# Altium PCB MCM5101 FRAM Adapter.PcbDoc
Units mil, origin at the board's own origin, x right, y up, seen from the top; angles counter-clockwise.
Board outline 630 x 1120 mil, 2 copper layers (Top Layer, Bottom Layer); 4 components, 17 nets, 52 pads, 5 vias.
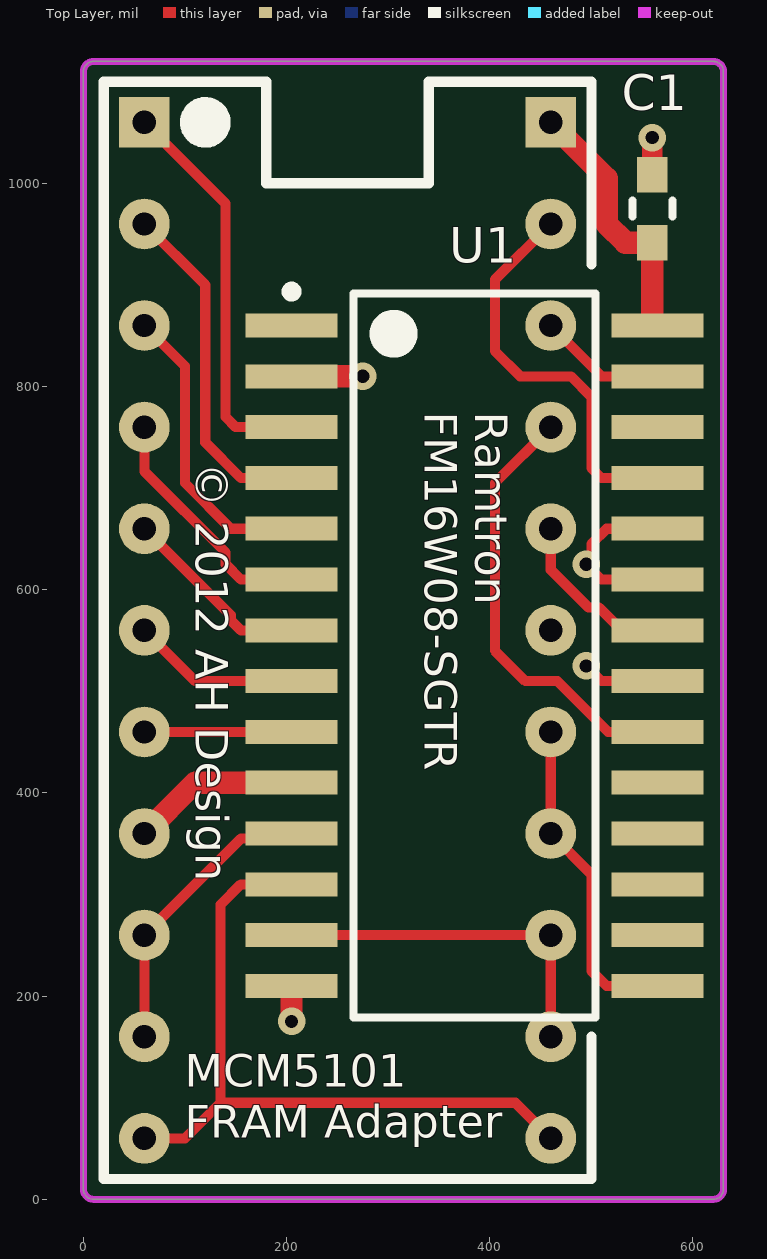
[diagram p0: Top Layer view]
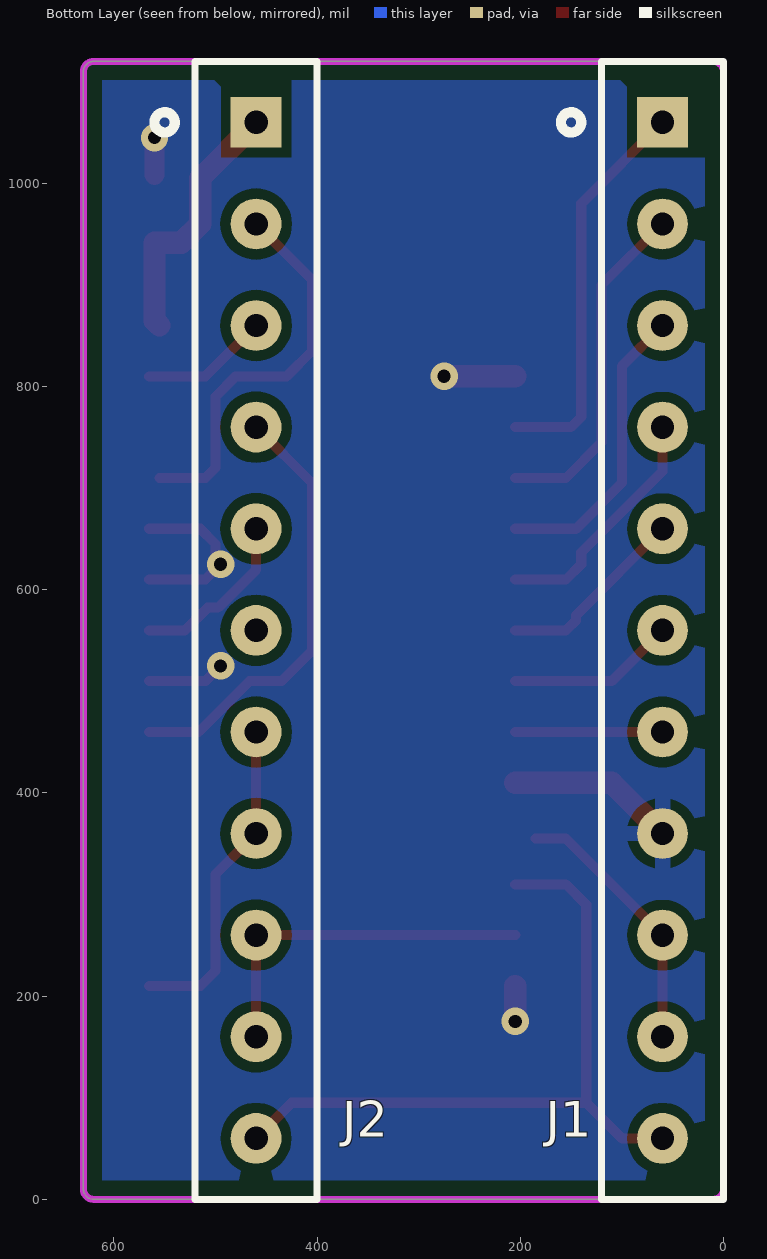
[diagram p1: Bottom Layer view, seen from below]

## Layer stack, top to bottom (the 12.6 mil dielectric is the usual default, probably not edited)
Top Layer: signal copper 1.4
Dielectric: dielectric 12.6, FR-4, Dk 4.8
Bottom Layer: signal copper 1.4

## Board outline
0,10 ccw(c10,10) 10,0 620,0 ccw(c620,10) 630,10 630,1110 ccw(c620,1110) 620,1120 10,1120 ccw(c10,1110) 0,1110

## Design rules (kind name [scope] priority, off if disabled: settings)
AcuteAngle [All] p1: minimum=6.00000000000000E+0001 checktracksonly=FALSE
Clearance Clearance_outline [OnLayer('Keep-Out Layer')] p1: gap=15
Clearance [All] p2: gap=10
MinimumAnnularRing [All] p1: minimumring=7
MinimumSolderMaskSliver [All] p1: minsoldermaskwidth=4
PolygonConnect PolygonConnect_1 [IsVia] p1: connectstyle=Direct reliefconductorwidth=10 reliefentries=4 polygonreliefangle="90 Angle"
PolygonConnect [All] p2: connectstyle=Relief reliefconductorwidth=15 reliefentries=4 polygonreliefangle="90 Angle"
RoomDefinition "MCM5101 FRAM Adapter" [InComponentClass('MCM5101 FRAM Adapter')] p1: confinementstyle=ConfineIn formatcopy=TRUE lockcomponents=FALSE outline -15,-15 635,-15 635,1135 -15,1135
RoutingVias [All] p1: holewidth=13 width=27 viastyle="Through Hole" minholewidth=13 minwidth=27 maxholewidth=28 maxwidth=50
SilkToSilkClearance [All] p1: silktosilkclearance=0
SilkscreenOverComponentPads [All] p1: minsilkscreentomaskgap=3
SolderMaskExpansion [All] p1: expansion=3
Width [All] p1: maxlimit=250 minlimit=10 preferedwidth=10
25 further rules are at their usual default settings.

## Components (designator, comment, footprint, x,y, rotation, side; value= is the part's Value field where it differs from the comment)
C1 "0.1uF" CC0603 560,975 r270 top
J1 "TS-111-T-AA" SAMTEC_TS-111-XX 60,560 r270 bottom
J2 "TS-111-T-AA" SAMTEC_TS-111-XX 460,560 r270 bottom
U1 "FM16W08-SGTR" SOIC127P1030X264-28N 385,535 r0 top

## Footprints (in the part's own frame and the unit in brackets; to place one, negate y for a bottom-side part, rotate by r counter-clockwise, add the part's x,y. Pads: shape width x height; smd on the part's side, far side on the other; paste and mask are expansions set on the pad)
CC0603 [mil] "Chip Capacitor, Body 1.6x0.8mm, IPC Medium Density"
  rect 35x30 smd: 1(-33.46,0) 2(33.46,0)
  silkscreen extent -8,-20 8,20, body extent -33,-19 33,19, height 24
SAMTEC_TS-111-XX [mil] "Samtec TS-111-XX series footprint"
  rect 50x50 hole 23: 1(-500,0)
  round 50 hole 23: 2(-400,0) 3(-300,0) 4(-200,0) 5(-100,0) 6(0,0) 7(100,0) 8(200,0) 9(300,0) 10(400,0) 11(500,0)
  silkscreen extent -560,-100 560,60, body extent -550,-50 550,50, height 325
SOIC127P1030X264-28N [mm] "SOIC, 28-Leads, Body 18.1x7.6mm (max), Pitch 1.27mm, IPC Medium Density"
  rect 2.3x0.6 smd: 1(-4.575,8.255) 2(-4.575,6.985) 3(-4.575,5.715) 4(-4.575,4.445) 5(-4.575,3.175) 6(-4.575,1.905) 7(-4.575,0.635) 8(-4.575,-0.635) 9(-4.575,-1.905) 10(-4.575,-3.175) 11(-4.575,-4.445) 12(-4.575,-5.715) 13(-4.575,-6.985) 14(-4.575,-8.255) 15(4.575,-8.255) 16(4.575,-6.985) 17(4.575,-5.715) 18(4.575,-4.445) 19(4.575,-3.175) 20(4.575,-1.905) 21(4.575,-0.635) 22(4.575,0.635) 23(4.575,1.905) 24(4.575,3.175) 25(4.575,4.445) 26(4.575,5.715) 27(4.575,6.985) 28(4.575,8.255)
  silkscreen extent -4.7,-9.05 3.03,9.23, body extent -3.79,-9.04 3.8,9.04, height 2.64

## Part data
C1: library part 0.1uF,10V,CC0603,X7R,+/-20%, "0.1uF 10V, in a CC0603, X7R ,+/-20%,LF"
J1 J2: library part Samtec_TS-111-T-AA, "PRECISION MACHINED TERMINAL STRIP, 0.018\" diameter post"
U1: "IC FRAM 64KBIT (8Kx8) 70NS 28SOIC"

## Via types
v1: diameter 27, hole 13, Top Layer to Bottom Layer, tented both sides, 5 vias

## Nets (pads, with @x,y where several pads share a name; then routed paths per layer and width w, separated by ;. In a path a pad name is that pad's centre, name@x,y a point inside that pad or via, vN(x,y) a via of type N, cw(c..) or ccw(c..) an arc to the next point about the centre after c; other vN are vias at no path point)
5101_A0: J1.4 U1.6 | length 239.2
  Top Layer w10: J1.4 60,716.57 140,636.57 140,625 155,610 U1.6
5101_A1: J1.3 U1.5 | length 295.1
  Top Layer w10: J1.3 100,820 100,705 145,660 U1.5
5101_A2: J1.2 U1.4 | length 339.2
  Top Layer w10: J1.2 120,900 120,745 155,710 U1.4
5101_A3: J1.1 U1.3 | length 392.2
  Top Layer w10: J1.1 140,980 140,770 150,760 U1.3
5101_A4: J2.2 U1.25 | length 390.7
  Top Layer w10: J2.2 405,905 405,835 430,810 480,810 500,790 500,720 510,710 U1.25@555.12,710
5101_A5: J1.5 U1.7 | length 189.2
  Top Layer w10: J1.5 145,575 145,570 155,560 U1.7
5101_A6: J1.6 U1.8 | length 165.6
  Top Layer w10: J1.6 110,510 U1.8
5101_A7: J1.7 U1.9 | length 144.9
  Top Layer w10: J1.7 U1.9
5101_CE#: J2.4 U1.20 | length 436
  Top Layer w10: J2.4 405,705 405,540 435,510 466.57,510 516.57,460 U1.20
5101_D0: J1.9 J1.10 U1.11 | length 264.4
  Top Layer w10: J1.10 J1.9 155,355 U1.11@185,355
5101_D1: J1.11 J2.11 U1.12 | length 702.2
  Top Layer w10: J1.11 100,60 135,95 ; U1.12 155,310 135,290 135,95 ; J2.11 425,95 135,95
5101_D2: J2.9 J2.10 U1.13 | length 355.1
  Top Layer w10: U1.13 J2.9 J2.10
5101_D3: J2.7 J2.8 U1.15 | length 322.9
  Top Layer w10: J2.7 J2.8 500,320 500,225 515,210 U1.15
5101_OE#: J2.5 U1.22 | length 170.1
  Top Layer w10: J2.5 460,619.69 497.35,582.35 507.65,582.35 530,560 U1.22
5101_R/W#: J2.3 U1.27 | length 125.8
  Top Layer w10: J2.3 510,810 U1.27
+5V: C1.2 J2.1 U1.28 | length 259
  Top Layer w22: J2.1 515,1005 515,960 533.46,941.54 C1.2 560,864.88 U1.28@555.12,860
GND: C1.1 J1.8 U1.2 U1.10 U1.14 U1.21 U1.23 U1.24 | length 560.3
  Top Layer w10: v1(495,525) 510,510 U1.21 ; U1.23 510,610 v1(495,625) 500,630 500,645 515,660 U1.24
  Top Layer w20: C1.1 v1(560,1045)
  Top Layer w22: J1.8 110,410 U1.10 ; v1(204.88,175.12) U1.14 ; U1.2 v1(275,810)
  Bottom Layer w10: v1@490,520 v1(495,525)
pads on no net: J2.6 U1.1 U1.16 U1.17 U1.18 U1.19 U1.26

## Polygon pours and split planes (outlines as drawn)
GND on Bottom Layer "GND" (solid, remove dead copper, pour order 2): 0,1120 0,0 600,0 630,0 630,70 630,1120 35,1120

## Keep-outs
Keep-Out Layer:
  the board outline again, w7

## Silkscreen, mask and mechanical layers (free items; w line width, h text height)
Top Overlay:
  circle w10: c120,1060 r5
  circle w10: c120,1060 r11.18
  circle w10: c120,1060 r20
  lines w10: 500,160 500,20 20,20 20,40 20,1100 180,1100 180,1000 340,1000 340,1100 500,1100 500,920
  text "FM16W08-SGTR" at 325,775 h55 r270
  text "Ramtron" at 375,775 h55 r270
  text "© 2012 AH Design" at 100,725 h55 r270
  text "MCM5101" at 100,100 h55
  text "FRAM Adapter" at 100,50 h55
Drill Drawing:
  text ".Legend" at 1175,25 h100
